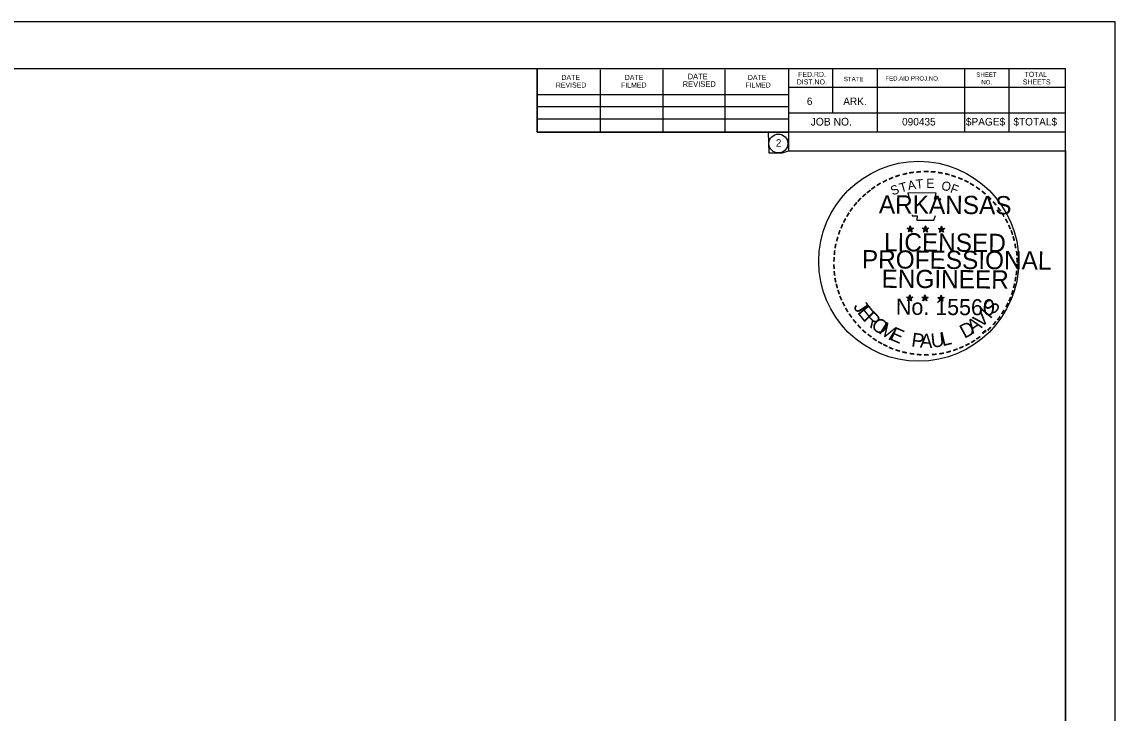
# Model space of a CAD drawing. Extents: x -1.3 to 32.7, y -0.7 to 21.3.
# Drawn here: x 15.72 to 32.74, y 10.51 to 21.27 of the extents above; entities that cross this region are included whole.
import ezdxf

# ---------------------------------------------------------------- set-up
doc = ezdxf.new("R2010")
doc.units = 0
for name, color, linetype in [('Level 1', 7, 'Continuous'), ('Level 49', 7, 'Continuous'), ('Level 62', 7, 'Continuous'), ('Level 63', 7, 'Continuous'), ('Stamp Mask', 7, 'Continuous')]:
    doc.layers.add(name, color=color, linetype=linetype)

msp = doc.modelspace()

# ---------------------------------------------------------------- linework, layer by layer
at = {"layer": 'Level 1'}
for p, q in [((0.346, 20.545), (31.964, 20.545)), ((23.738, 19.557), (23.738, 20.545)), ((24.724, 19.557), (24.724, 20.525)), ((25.7, 19.557), (25.7, 20.525)), ((26.668, 19.557), (26.668, 20.525)), ((27.654, 20.545), (27.654, 19.265)), ((28.338, 20.545), (28.338, 19.851)), ((29.032, 20.545), (29.032, 19.557)), ((30.39, 20.545), (30.39, 19.557)), ((31.084, 20.545), (31.084, 19.557)), ((31.964, -0.001), (31.964, 20.545)), ((23.738, 20.143), (27.654, 20.143)), ((31.964, 20.251), (27.654, 20.251)), ((31.964, 20.253), (31.964, 20.253)), ((23.738, 19.957), (27.654, 19.957)), ((23.738, 19.557), (23.738, 19.763)), ((23.738, 19.763), (27.654, 19.763)), ((31.964, 19.851), (27.654, 19.851)), ((31.964, 19.557), (23.738, 19.557)), ((27.654, 19.557), (27.654, 19.274)), ((27.654, 19.265), (31.964, 19.265))]:
    msp.add_line(p, q, dxfattribs=at)
msp.add_lwpolyline([(0.346, 20.545), (23.738, 20.545), (23.738, 19.557), (27.654, 19.557), (27.654, 19.265), (31.964, 19.265), (31.964, 10.293), (0.346, 10.293)], close=True, dxfattribs=at)
msp.add_circle((27.494, 19.379), 0.147, dxfattribs=at)
at = {"layer": 'Level 49'}
for p, q in [((29.497, 18.062), (29.548, 18.046)), ((29.497, 18.062), (29.534, 18.06)), ((29.497, 18.062), (29.534, 18.058)), ((29.497, 18.062), (29.531, 18.053)), ((29.497, 18.062), (29.531, 18.048)), ((29.497, 18.062), (29.531, 18.046)), ((29.497, 18.062), (29.531, 18.041)), ((29.518, 18.004), (29.548, 18.046)), ((29.518, 18.004), (29.531, 18.044)), ((29.548, 18.1), (29.541, 18.062)), ((29.548, 18.1), (29.541, 18.065)), ((29.548, 18.1), (29.545, 18.065)), ((29.548, 18.046), (29.548, 18.1)), ((29.548, 18.1), (29.557, 18.062)), ((29.548, 18.1), (29.555, 18.065)), ((29.548, 18.1), (29.55, 18.065)), ((29.597, 18.062), (29.548, 18.046)), ((29.578, 18.002), (29.548, 18.046)), ((29.597, 18.062), (29.552, 18.058)), ((29.597, 18.062), (29.557, 18.055)), ((29.597, 18.062), (29.557, 18.051)), ((29.578, 18.002), (29.557, 18.044)), ((29.578, 18.002), (29.562, 18.046)), ((29.597, 18.062), (29.564, 18.051)), ((29.597, 18.062), (29.569, 18.048)), ((29.597, 18.062), (29.571, 18.046)), ((29.734, 18.06), (29.784, 18.046)), ((29.734, 18.06), (29.77, 18.058)), ((29.734, 18.06), (29.77, 18.055)), ((29.734, 18.06), (29.77, 18.053)), ((29.734, 18.06), (29.769, 18.046)), ((29.734, 18.06), (29.769, 18.044)), ((29.734, 18.06), (29.769, 18.039)), ((29.755, 18.002), (29.784, 18.046)), ((29.784, 18.097), (29.777, 18.06)), ((29.784, 18.097), (29.777, 18.062)), ((29.784, 18.097), (29.779, 18.062)), ((29.784, 18.046), (29.784, 18.097)), ((29.784, 18.097), (29.793, 18.06)), ((29.784, 18.097), (29.791, 18.062)), ((29.784, 18.097), (29.786, 18.062)), ((29.833, 18.06), (29.784, 18.046)), ((29.814, 18.002), (29.784, 18.046)), ((29.833, 18.06), (29.79, 18.058)), ((29.833, 18.06), (29.793, 18.053)), ((29.833, 18.06), (29.793, 18.051)), ((29.814, 18.002), (29.793, 18.044)), ((29.814, 18.002), (29.798, 18.044)), ((29.833, 18.06), (29.8, 18.048)), ((29.833, 18.06), (29.805, 18.046)), ((29.833, 18.06), (29.807, 18.044)), ((29.984, 18.058), (30.035, 18.041)), ((29.984, 18.058), (30.024, 18.053)), ((29.984, 18.058), (30.021, 18.051)), ((29.984, 18.058), (30.021, 18.048)), ((29.984, 18.058), (30.019, 18.044)), ((29.984, 18.058), (30.019, 18.039)), ((29.984, 18.058), (30.019, 18.039)), ((30.035, 18.093), (30.026, 18.06)), ((30.035, 18.093), (30.031, 18.058)), ((30.035, 18.093), (30.031, 18.058)), ((30.035, 18.041), (30.035, 18.093)), ((30.035, 18.093), (30.045, 18.058)), ((30.035, 18.093), (30.042, 18.058)), ((30.035, 18.093), (30.038, 18.058)), ((30.084, 18.058), (30.035, 18.041)), ((30.084, 18.058), (30.04, 18.053)), ((30.084, 18.058), (30.045, 18.051)), ((30.084, 18.058), (30.045, 18.046)), ((30.084, 18.058), (30.052, 18.044)), ((30.084, 18.058), (30.054, 18.044)), ((30.084, 18.058), (30.059, 18.041)), ((29.518, 18.004), (29.534, 18.039)), ((29.518, 18.004), (29.536, 18.037)), ((29.518, 18.004), (29.541, 18.034)), ((29.518, 18.004), (29.548, 18.034)), ((29.518, 18.004), (29.548, 18.03)), ((29.578, 18.002), (29.548, 18.034)), ((29.578, 18.002), (29.548, 18.03)), ((29.578, 18.002), (29.552, 18.034)), ((29.578, 18.002), (29.557, 18.039)), ((29.755, 18.002), (29.77, 18.041)), ((29.755, 18.002), (29.77, 18.039)), ((29.755, 18.002), (29.772, 18.037)), ((29.755, 18.002), (29.777, 18.032)), ((29.755, 18.002), (29.784, 18.032)), ((29.755, 18.002), (29.784, 18.03)), ((29.814, 18.002), (29.784, 18.032)), ((29.814, 18.002), (29.784, 18.03)), ((29.814, 18.002), (29.79, 18.032)), ((29.814, 18.002), (29.793, 18.037)), ((30.003, 18), (30.035, 18.041)), ((30.003, 18), (30.021, 18.039)), ((30.003, 18), (30.024, 18.034)), ((30.003, 18), (30.024, 18.032)), ((30.003, 18), (30.035, 18.032)), ((30.003, 18), (30.031, 18.03)), ((30.003, 18), (30.038, 18.025)), ((30.063, 18), (30.035, 18.041)), ((30.063, 18), (30.035, 18.032)), ((30.063, 18), (30.035, 18.025)), ((30.063, 18), (30.04, 18.03)), ((30.063, 18), (30.045, 18.039)), ((30.063, 18), (30.045, 18.034)), ((30.063, 18), (30.049, 18.039)), ((29.541, 17.026), (29.531, 16.991)), ((29.541, 17.026), (29.534, 16.987)), ((29.541, 17.026), (29.536, 16.987)), ((29.541, 16.971), (29.541, 17.026)), ((29.541, 17.026), (29.548, 16.987)), ((29.541, 17.026), (29.548, 16.987)), ((29.541, 17.026), (29.541, 16.987)), ((29.777, 17.022), (29.769, 16.987)), ((29.777, 17.022), (29.77, 16.987)), ((29.777, 17.022), (29.772, 16.987)), ((29.777, 16.971), (29.777, 17.022)), ((29.777, 17.022), (29.784, 16.985)), ((29.777, 17.022), (29.784, 16.985)), ((29.777, 17.022), (29.777, 16.987)), ((30.028, 17.02), (30.019, 16.984)), ((30.028, 17.02), (30.021, 16.984)), ((30.028, 17.02), (30.024, 16.984)), ((30.028, 16.966), (30.028, 17.02)), ((30.028, 17.02), (30.035, 16.984)), ((30.028, 17.02), (30.035, 16.984)), ((30.028, 17.02), (30.028, 16.984)), ((29.49, 16.987), (29.541, 16.971)), ((29.49, 16.987), (29.527, 16.985)), ((29.49, 16.987), (29.525, 16.98)), ((29.49, 16.987), (29.525, 16.98)), ((29.49, 16.987), (29.525, 16.973)), ((29.49, 16.987), (29.525, 16.971)), ((29.49, 16.987), (29.525, 16.97)), ((29.508, 16.933), (29.541, 16.971)), ((29.508, 16.933), (29.525, 16.971)), ((29.508, 16.933), (29.527, 16.964)), ((29.508, 16.933), (29.529, 16.964)), ((29.508, 16.933), (29.541, 16.963)), ((29.508, 16.933), (29.534, 16.959)), ((29.508, 16.933), (29.541, 16.957)), ((29.569, 16.929), (29.538, 16.957)), ((29.59, 16.987), (29.541, 16.971)), ((29.569, 16.929), (29.541, 16.971)), ((29.569, 16.929), (29.541, 16.959)), ((29.569, 16.929), (29.543, 16.959)), ((29.59, 16.987), (29.545, 16.985)), ((29.59, 16.987), (29.548, 16.98)), ((29.59, 16.987), (29.548, 16.978)), ((29.569, 16.929), (29.548, 16.971)), ((29.569, 16.929), (29.548, 16.964)), ((29.59, 16.987), (29.555, 16.977)), ((29.569, 16.929), (29.555, 16.971)), ((29.59, 16.987), (29.559, 16.973)), ((29.59, 16.987), (29.562, 16.971)), ((29.727, 16.987), (29.777, 16.971)), ((29.727, 16.987), (29.763, 16.984)), ((29.727, 16.987), (29.763, 16.98)), ((29.727, 16.987), (29.763, 16.978)), ((29.727, 16.987), (29.762, 16.973)), ((29.727, 16.987), (29.762, 16.97)), ((29.727, 16.987), (29.762, 16.966)), ((29.744, 16.929), (29.777, 16.971)), ((29.744, 16.929), (29.763, 16.97)), ((29.744, 16.929), (29.763, 16.963)), ((29.744, 16.929), (29.765, 16.963)), ((29.744, 16.929), (29.77, 16.959)), ((29.744, 16.929), (29.777, 16.959)), ((29.744, 16.929), (29.777, 16.956)), ((29.805, 16.929), (29.776, 16.956)), ((29.825, 16.985), (29.777, 16.971)), ((29.805, 16.929), (29.777, 16.971)), ((29.805, 16.929), (29.777, 16.959)), ((29.805, 16.929), (29.779, 16.959)), ((29.825, 16.985), (29.783, 16.985)), ((29.825, 16.985), (29.784, 16.978)), ((29.825, 16.985), (29.784, 16.978)), ((29.805, 16.929), (29.784, 16.97)), ((29.805, 16.929), (29.784, 16.964)), ((29.825, 16.985), (29.791, 16.973)), ((29.805, 16.929), (29.791, 16.97)), ((29.825, 16.985), (29.797, 16.971)), ((29.825, 16.985), (29.798, 16.97)), ((29.977, 16.984), (30.028, 16.966)), ((29.977, 16.984), (30.014, 16.98)), ((29.977, 16.984), (30.014, 16.977)), ((29.977, 16.984), (30.012, 16.973)), ((29.977, 16.984), (30.012, 16.97)), ((29.977, 16.984), (30.01, 16.966)), ((29.977, 16.984), (30.01, 16.963)), ((29.996, 16.926), (30.028, 16.966)), ((29.996, 16.926), (30.012, 16.966)), ((29.996, 16.926), (30.014, 16.959)), ((29.996, 16.926), (30.017, 16.959)), ((29.996, 16.926), (30.021, 16.956)), ((29.996, 16.926), (30.026, 16.956)), ((29.996, 16.926), (30.028, 16.952)), ((30.056, 16.926), (30.026, 16.956)), ((30.056, 16.926), (30.026, 16.952)), ((30.077, 16.984), (30.028, 16.966)), ((30.056, 16.926), (30.028, 16.966)), ((30.056, 16.926), (30.031, 16.956)), ((30.077, 16.984), (30.033, 16.98)), ((30.077, 16.984), (30.035, 16.977)), ((30.077, 16.984), (30.035, 16.973)), ((30.056, 16.926), (30.035, 16.959)), ((30.056, 16.926), (30.038, 16.966)), ((30.056, 16.926), (30.04, 16.966)), ((30.077, 16.984), (30.045, 16.971)), ((30.077, 16.984), (30.047, 16.966)), ((30.077, 16.984), (30.049, 16.966))]:
    msp.add_line(p, q, dxfattribs=at)
for points in [[(29.508, 18.613), (29.543, 18.494)], [(30.005, 18.478), (30.026, 18.52), (29.926, 18.515), (29.949, 18.609), (29.508, 18.613)], [(29.576, 18.268), (29.576, 18.254), (29.655, 18.252), (29.648, 18.188), (29.912, 18.186), (29.94, 18.259)], [(29.548, 18.1), (29.578, 18.002), (29.497, 18.062), (29.597, 18.062), (29.518, 18.004), (29.548, 18.1)], [(29.784, 18.097), (29.814, 18.002), (29.734, 18.06), (29.833, 18.06), (29.755, 18.002), (29.784, 18.097)], [(30.035, 18.093), (30.063, 18), (29.984, 18.058), (30.084, 18.058), (30.003, 18), (30.035, 18.093)], [(29.541, 17.026), (29.569, 16.929), (29.49, 16.987), (29.59, 16.987), (29.508, 16.933), (29.541, 17.026)], [(29.777, 17.022), (29.805, 16.929), (29.727, 16.987), (29.825, 16.985), (29.744, 16.929), (29.777, 17.022)], [(30.028, 17.02), (30.056, 16.926), (29.977, 16.984), (30.077, 16.984), (29.996, 16.926), (30.028, 17.02)], [(30.684, 16.415), (30.677, 16.438), (30.719, 16.473)], [(30.715, 16.478), (30.722, 16.457), (30.68, 16.42)], [(30.722, 16.46), (30.68, 16.424)], [(30.722, 16.457), (30.682, 16.422)]]:
    msp.add_lwpolyline(points, dxfattribs=at)
for centre, radius in [((29.549, 18.045), 0.0244), ((29.549, 18.045), 0.0221), ((29.549, 18.045), 0.0205), ((29.549, 18.045), 0.0188), ((29.549, 18.045), 0.0164), ((29.549, 18.045), 0.0152), ((29.549, 18.045), 0.014), ((29.549, 18.045), 0.0121), ((29.549, 18.045), 0.0106), ((29.549, 18.045), 0.00881), ((29.549, 18.045), 0.00702), ((29.549, 18.045), 0.00524), ((29.549, 18.045), 0.0042), ((29.549, 18.045), 0.00204), ((29.786, 18.043), 0.0244), ((29.786, 18.043), 0.0221), ((29.786, 18.043), 0.0205), ((29.786, 18.043), 0.0188), ((29.786, 18.043), 0.0164), ((29.786, 18.043), 0.0152), ((29.786, 18.043), 0.014), ((29.786, 18.043), 0.0121), ((29.786, 18.043), 0.0106), ((29.786, 18.043), 0.00881), ((29.786, 18.043), 0.00702), ((29.786, 18.043), 0.00524), ((29.786, 18.043), 0.0042), ((29.786, 18.043), 0.00204), ((30.036, 18.04), 0.0244), ((30.036, 18.04), 0.0221), ((30.036, 18.04), 0.0205), ((30.036, 18.04), 0.0188), ((30.036, 18.04), 0.0164), ((30.036, 18.04), 0.0152), ((30.036, 18.04), 0.014), ((30.036, 18.04), 0.0121), ((30.036, 18.04), 0.0106), ((30.036, 18.04), 0.00881), ((30.036, 18.04), 0.00702), ((30.036, 18.04), 0.00524), ((30.036, 18.04), 0.0042), ((30.036, 18.04), 0.00204), ((29.541, 16.971), 0.0244), ((29.541, 16.971), 0.0221), ((29.541, 16.971), 0.0205), ((29.541, 16.971), 0.0188), ((29.541, 16.971), 0.0164), ((29.541, 16.971), 0.0152), ((29.541, 16.971), 0.014), ((29.541, 16.971), 0.0121), ((29.541, 16.971), 0.0106), ((29.541, 16.971), 0.00881), ((29.541, 16.971), 0.00702), ((29.541, 16.971), 0.00524), ((29.541, 16.971), 0.0042), ((29.541, 16.971), 0.00204), ((29.778, 16.97), 0.0244), ((29.778, 16.97), 0.0221), ((29.778, 16.97), 0.0205), ((29.778, 16.97), 0.0188), ((29.778, 16.97), 0.0164), ((29.778, 16.97), 0.0152), ((29.778, 16.97), 0.014), ((29.778, 16.97), 0.0121), ((29.778, 16.97), 0.0106), ((29.778, 16.97), 0.00881), ((29.778, 16.97), 0.00702), ((29.778, 16.97), 0.00524), ((29.778, 16.97), 0.0042), ((29.778, 16.97), 0.00204), ((30.028, 16.966), 0.0244), ((30.028, 16.966), 0.0221), ((30.028, 16.966), 0.0205), ((30.028, 16.966), 0.0188), ((30.028, 16.966), 0.0164), ((30.028, 16.966), 0.0152), ((30.028, 16.966), 0.014), ((30.028, 16.966), 0.0121), ((30.028, 16.966), 0.0106), ((30.028, 16.966), 0.00881), ((30.028, 16.966), 0.00702), ((30.028, 16.966), 0.00524), ((30.028, 16.966), 0.0042), ((30.028, 16.966), 0.00204)]:
    msp.add_circle(centre, radius, dxfattribs=at)
at = {"layer": 'Level 62'}
msp.add_lwpolyline([(0.346, 20.545), (23.738, 20.545), (23.738, 20.545), (23.738, 19.557), (23.738, 19.557), (27.335, 19.557), (27.346, 19.232), (27.559, 19.232), (27.654, 19.265), (31.964, 19.265), (31.964, 10.293), (0.346, 10.293)], close=True, dxfattribs=at)
at = {"layer": 'Level 63'}
msp.add_lwpolyline([(-1.263, -0.727), (32.737, -0.727), (32.737, 21.273), (-1.263, 21.273)], close=True, dxfattribs=at)
at = {"layer": 'Stamp Mask'}
msp.add_circle((29.679, 17.546), 1.557, dxfattribs=at)

# ---------------------------------------------------------------- texts
at = {"layer": 'Level 1'}
for s, height, p in [('DATE', 0.0782, (24.118, 20.369)), ('DATE', 0.0782, (25.104, 20.369)), ('DATE', 0.0879, (26.082, 20.379)), ('DATE', 0.0782, (27.02, 20.369)), ('FED.RD.', 0.0782, (27.802, 20.417)), ('FED.AID PROJ.NO.', 0.0684, (29.16, 20.359)), ('SHEET', 0.0684, (30.576, 20.417)), ('TOTAL', 0.0782, (31.328, 20.417)), ('REVISED', 0.0782, (24.03, 20.251)), ('FILMED', 0.0782, (25.046, 20.251)), ('REVISED', 0.0879, (26.004, 20.261)), ('FILMED', 0.0782, (26.98, 20.251)), ('DIST.NO.', 0.0782, (27.782, 20.299)), ('STATE', 0.0684, (28.514, 20.349)), ('NO.', 0.0684, (30.654, 20.299)), ('SHEETS', 0.0782, (31.3, 20.299)), ('6', 0.117, (27.938, 19.977)), ('ARK.', 0.1172, (28.504, 19.977)), ('JOB NO.', 0.12, (27.997, 19.659)), ('090435', 0.1172, (29.42, 19.66)), ('$PAGE$', 0.1172, (30.414, 19.66)), ('$TOTAL$', 0.1172, (31.153, 19.66)), ('2', 0.117, (27.455, 19.329))]:
    msp.add_text(s, height=height, dxfattribs=at).set_placement(p)
at = {"layer": 'Level 49'}
for s, height, rotation, p in [('-', 0.227, 18.7785, (29.329, 18.776)), ('-', 0.227, 13.2326, (29.436, 18.809)), ('-', 0.227, 9.8217, (29.531, 18.832)), ('-', 0.227, 5.4992, (29.636, 18.846)), ('-', 0.227, 359.7886, (29.744, 18.856)), ('-', 0.227, 357.3454, (29.849, 18.853)), ('-', 0.227, 351.7641, (29.952, 18.844)), ('-', 0.227, 346.8073, (30.056, 18.828)), ('-', 0.227, 341.9386, (30.145, 18.804)), ('-', 0.227, 33.666, (29.063, 18.643)), ('-', 0.227, 28.3942, (29.149, 18.693)), ('-', 0.227, 23.9096, (29.238, 18.737)), ('S', 0.142, 21.1964, (29.272, 18.569)), ('T', 0.142, 16.006, (29.401, 18.616)), ('A', 0.142, 10.8156, (29.52, 18.651)), ('T', 0.142, 5.6252, (29.641, 18.674)), ('E', 0.142, 0.4347, (29.797, 18.688)), ('O', 0.142, 350.0539, (30.024, 18.658)), ('F', 0.142, 339.6731, (30.159, 18.623)), ('-', 0.227, 337.4575, (30.248, 18.772)), ('-', 0.227, 333.7235, (30.339, 18.735)), ('-', 0.227, 329.2433, (30.42, 18.693)), ('-', 0.227, 42.5646, (28.852, 18.475)), ('-', 0.227, 38.5531, (28.915, 18.532)), ('-', 0.227, 35.8341, (28.981, 18.587)), ('ARKANSAS', 0.2836, 359.6024, (29.058, 18.291)), ('-', 0.227, 325.4651, (30.511, 18.639)), ('-', 0.227, 320.1321, (30.596, 18.58)), ('-', 0.227, 315.181, (30.682, 18.51)), ('-', 0.227, 53.8349, (28.67, 18.259)), ('-', 0.227, 50.2166, (28.729, 18.34)), ('-', 0.227, 48.0254, (28.787, 18.408)), ('-', 0.227, 309.4821, (30.761, 18.431)), ('-', 0.227, 306.2546, (30.833, 18.345)), ('-', 0.227, 62.4738, (28.58, 18.097)), ('-', 0.227, 57.673, (28.624, 18.182)), ('-', 0.198, 303.2777, (30.903, 18.263)), ('-', 0.227, 299.2708, (30.946, 18.177)), ('-', 0.227, 67.3767, (28.544, 18.011)), ('-', 0.227, 294.2652, (30.992, 18.09)), ('-', 0.227, 75.0634, (28.482, 17.82)), ('-', 0.227, 71.9969, (28.51, 17.922)), ('LICENSED', 0.2836, 359.6024, (29.138, 17.703)), ('-', 0.227, 290.1752, (31.03, 18.011)), ('-', 0.227, 284.7257, (31.06, 17.927)), ('-', 0.227, 84.7887, (28.451, 17.622)), ('-', 0.227, 80.8037, (28.461, 17.72)), ('PROFESSIONAL', 0.28356, 359.6024, (28.794, 17.437)), ('-', 0.227, 280.1517, (31.088, 17.82)), ('-', 0.227, 276.1986, (31.113, 17.712)), ('-', 0.227, 88.6646, (28.447, 17.523)), ('-', 0.227, 273.9325, (31.12, 17.608)), ('-', 0.227, 93.7983, (28.451, 17.419)), ('-', 0.227, 98.5503, (28.461, 17.323)), ('ENGINEER', 0.2836, 359.6024, (29.1, 17.134)), ('-', 0.227, 263.1196, (31.12, 17.426)), ('-', 0.227, 269.5431, (31.123, 17.521)), ('-', 0.227, 101.3173, (28.477, 17.22)), ('-', 0.227, 105.0602, (28.502, 17.136)), ('-', 0.227, 255.365, (31.092, 17.237)), ('-', 0.227, 260.5977, (31.107, 17.334)), ('-', 0.227, 108.6898, (28.531, 17.048)), ('-', 0.227, 252.4705, (31.067, 17.134)), ('-', 0.227, 113.6667, (28.566, 16.961)), ('-', 0.227, 115.3313, (28.61, 16.873)), ('J', 0.218, 303.9209, (28.653, 16.84)), ('E', 0.218, 308.618, (28.715, 16.749)), ('No. 15560', 0.2495, 359.6024, (29.324, 16.715)), ('S', 0.218, 53.5227, (30.845, 16.701)), ('-', 0.227, 244.2221, (30.995, 16.95)), ('-', 0.227, 247.4911, (31.036, 17.038)), ('-', 0.227, 120.0495, (28.659, 16.789)), ('-', 0.227, 125.4958, (28.717, 16.711)), ('R', 0.218, 314.7784, (28.806, 16.637)), ('V', 0.218, 41.4844, (30.646, 16.501)), ('I', 0.218, 49.9999, (30.791, 16.638)), ('-', 0.227, 233.4476, (30.885, 16.753)), ('-', 0.227, 238.6736, (30.939, 16.845)), ('-', 0.227, 130.3205, (28.78, 16.632)), ('-', 0.227, 133.8262, (28.853, 16.555)), ('O', 0.218, 321.6761, (28.922, 16.524)), ('M', 0.218, 328.1357, (29.043, 16.432)), ('E', 0.218, 336.4966, (29.212, 16.334)), ('D', 0.218, 28.5809, (30.392, 16.338)), ('A', 0.218, 34.8903, (30.521, 16.411)), ('-', 0.227, 225.3677, (30.752, 16.593)), ('-', 0.227, 233.4476, (30.819, 16.676)), ('-', 0.227, 138.5362, (28.925, 16.488)), ('-', 0.227, 144.2487, (29.007, 16.431)), ('-', 0.227, 147.6922, (29.084, 16.376)), ('P', 0.218, 351.9783, (29.556, 16.222)), ('A', 0.218, 357.9896, (29.696, 16.204)), ('U', 0.218, 5.7635, (29.878, 16.202)), ('L', 0.218, 13.0992, (30.049, 16.223)), ('-', 0.227, 215.3387, (30.598, 16.455)), ('-', 0.227, 151.1728, (29.165, 16.331)), ('-', 0.227, 154.2026, (29.242, 16.294)), ('-', 0.227, 158.1636, (29.329, 16.256)), ('-', 0.227, 162.4007, (29.427, 16.226)), ('-', 0.227, 200.3208, (30.267, 16.27)), ('-', 0.227, 203.854, (30.355, 16.308)), ('-', 0.227, 206.9592, (30.444, 16.352)), ('-', 0.227, 211.8515, (30.523, 16.401)), ('-', 0.227, 167.1579, (29.527, 16.203)), ('-', 0.227, 172.7179, (29.636, 16.187)), ('-', 0.227, 176.1207, (29.742, 16.177)), ('-', 0.227, 181.1942, (29.847, 16.18)), ('-', 0.227, 185.4191, (29.963, 16.189)), ('-', 0.227, 190.8882, (30.068, 16.207)), ('-', 0.227, 195.0767, (30.171, 16.235))]:
    msp.add_text(s, height=height, rotation=rotation, dxfattribs=at).set_placement(p)

doc.saveas('drawing.dxf')
